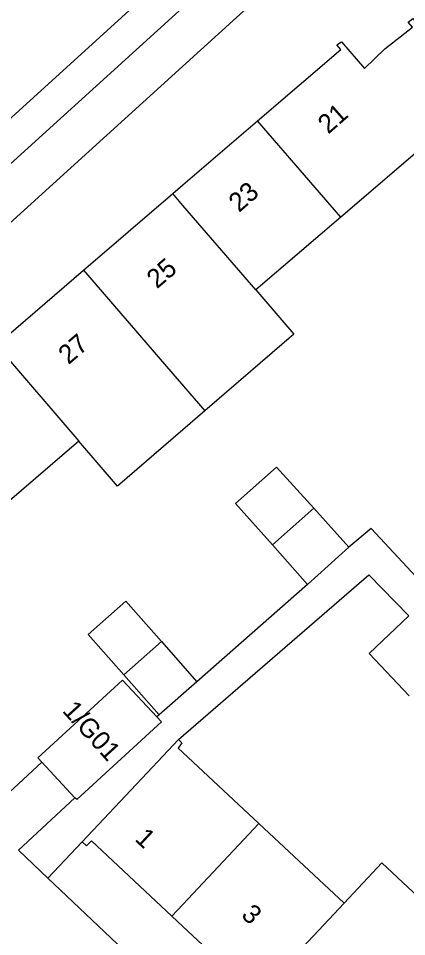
# Model space of a CAD drawing. Extents: x 157466 to 158888, y 383063 to 384677.
# Drawn here: x 157991.34 to 158011.77, y 383616.61 to 383664.97 of the extents above; entities that cross this region are included whole.
import ezdxf

# ---------------------------------------------------------------- set-up
doc = ezdxf.new("R2010")
doc.units = 0
for name, color, linetype in [('IMGEO_Muur', 7, 'Continuous'), ('IMGEO_Pand', 7, 'Continuous'), ('IMGEO_Pand_nummerreeks', 7, 'Continuous'), ('IMGEO_Rijbaan_lokaal_open', 7, 'Continuous'), ('IMGEO_Voetpad_open', 7, 'Continuous')]:
    doc.layers.add(name, color=color, linetype=linetype)

msp = doc.modelspace()

# ---------------------------------------------------------------- linework, layer by layer
at = {"layer": 'IMGEO_Muur'}
msp.add_lwpolyline([(157992.577, 383625.793), (157989.635, 383623.079)], dxfattribs=at)
at = {"layer": 'IMGEO_Pand'}
for points in [[(158003.932, 383659.572), (158008.317, 383663.337), (158008.105, 383663.584), (158008.353, 383663.735), (158009.559, 383662.338), (158010.633, 383663.362), (158012.09, 383664.505), (158011.854, 383664.762), (158012.101, 383664.966), (158017.498, 383658.647), (158014.531, 383656.155), (158012.982, 383657.958), (158012.714, 383658.27), (158008.303, 383654.494)], [(157999.469, 383655.739), (158000, 383656.195), (158003.932, 383659.572)], [(158008.303, 383654.494), (158003.932, 383659.572)], [(157994.775, 383651.708), (157999.469, 383655.739)], [(158003.834, 383650.668), (158000, 383655.122), (157999.469, 383655.739)], [(158008.303, 383654.494), (158003.834, 383650.668)], [(157990.169, 383647.753), (157994.775, 383651.708)], [(157994.775, 383651.708), (157999.134, 383646.644), (158001.152, 383644.3)], [(158003.834, 383650.668), (158005.84, 383648.337), (158001.152, 383644.3)], [(157990.169, 383647.753), (157994.521, 383642.696)], [(158001.152, 383644.3), (158000, 383643.308), (157996.55, 383640.339), (157994.521, 383642.696)], [(157994.521, 383642.696), (157989.977, 383638.805)], [(158004.706, 383637.238), (158002.767, 383639.42), (158004.932, 383641.343), (158006.882, 383639.173)], [(158004.706, 383637.238), (158006.882, 383639.173)], [(158006.882, 383639.173), (158008.731, 383637.116)], [(158006.554, 383635.159), (158004.706, 383637.238)], [(158008.731, 383637.116), (158006.554, 383635.159)], [(157996.888, 383630.391), (157995.009, 383632.528), (157996.988, 383634.286), (157998.867, 383632.15)], [(158011.897, 383633.502), (158009.801, 383631.523), (158011.909, 383629.29)], [(157996.888, 383630.391), (157998.867, 383632.15)], [(157998.867, 383632.15), (158000.731, 383630.031)], [(157998.743, 383628.283), (157996.888, 383630.391)], [(157992.577, 383625.793), (157992.363, 383626.022), (157996.825, 383630.112), (157998.632, 383628.179)], [(158000.731, 383630.031), (157998.743, 383628.283)], [(157998.632, 383628.179), (157998.874, 383627.92), (157994.412, 383623.83), (157994.313, 383623.929)], [(157994.701, 383621.602), (157998.127, 383625.245), (157999.764, 383626.986)], [(157999.764, 383626.986), (157999.939, 383626.817), (157999.748, 383626.538), (158000, 383626.302), (158003.991, 383622.571)], [(157992.577, 383625.793), (157994.313, 383623.929)], [(157999.422, 383617.69), (158000, 383618.308), (158003.991, 383622.571)], [(158003.991, 383622.571), (158008.48, 383618.374)], [(157999.422, 383617.69), (157995.185, 383621.664), (157994.927, 383621.39), (157994.701, 383621.602)], [(158008.48, 383618.374), (158010.465, 383620.494), (158014.853, 383616.391), (158012.868, 383614.271)], [(158008.48, 383618.374), (158003.904, 383613.486)], [(158003.904, 383613.486), (158000, 383617.148), (157999.422, 383617.69)]]:
    msp.add_lwpolyline(points, dxfattribs=at)
at = {"layer": 'IMGEO_Rijbaan_lokaal_open'}
for points in [[(157975.694, 383645.872), (158005.476, 383672.949)], [(157989.635, 383623.079), (157992.577, 383625.793)], [(157994.313, 383623.929), (157991.341, 383621.162)]]:
    msp.add_lwpolyline(points, dxfattribs=at)
at = {"layer": 'IMGEO_Voetpad_open'}
for points in [[(157976.459, 383641.091), (158008.69, 383670.365), (158009.061, 383670.029)], [(158004.712, 383669.838), (157978.795, 383646.296)], [(158013.201, 383634.565), (158009.916, 383638.107), (158008.731, 383637.116)], [(157999.764, 383626.986), (158009.777, 383635.669), (158011.897, 383633.502)], [(158006.554, 383635.159), (158000.731, 383630.031)], [(157998.743, 383628.283), (157998.632, 383628.179)], [(157992.898, 383619.685), (157994.701, 383621.602)], [(157992.898, 383619.685), (157991.341, 383621.162)], [(158021.258, 383592.581), (158020.837, 383593.194), (157992.898, 383619.685)]]:
    msp.add_lwpolyline(points, dxfattribs=at)

# ---------------------------------------------------------------- texts
at = {"layer": 'IMGEO_Pand_nummerreeks'}
for s, rotation, p in [('21', 41.3175, (158007.65, 383658.843)), ('23', 41.3175, (158002.956, 383654.717)), ('25', 40.6571, (157998.633, 383650.697)), ('27', 40.6514, (157993.982, 383646.704)), ('1/G01', 312.1351, (157993.614, 383628.479)), ('1', 317.0218, (157997.423, 383621.7)), ('3', 317.0296, (158003.02, 383617.688))]:
    msp.add_text(s, height=1, rotation=rotation, dxfattribs=at).set_placement(p)

doc.saveas('drawing.dxf')
